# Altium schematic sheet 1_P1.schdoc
size 307 x 218 mm; Symbol: Sheet-Symbol_A4; Device: Sheet-Symbol_A4; Company: SEIKAN Inc.; Drawed: Feryquence; Reviewed: Feryquence; Version: V2.06; Page Size: A4; @Project Name: Akari NEW; @Page Count: 1; @Update Date: 2025-08-06; @Create Date: 2025-07-07; @Schematic Name: Schematic1_1; @Page No: 1; @Page Name: P1; @Board Name: Plus; @Create Time: 18:45:47; @Update Time: 02:56:45; Width: 1170; Height: 825; Region Start: 1; X Region Count: 6; Y Region Count: 4; Blade Width: 10; Title Block Position: 3
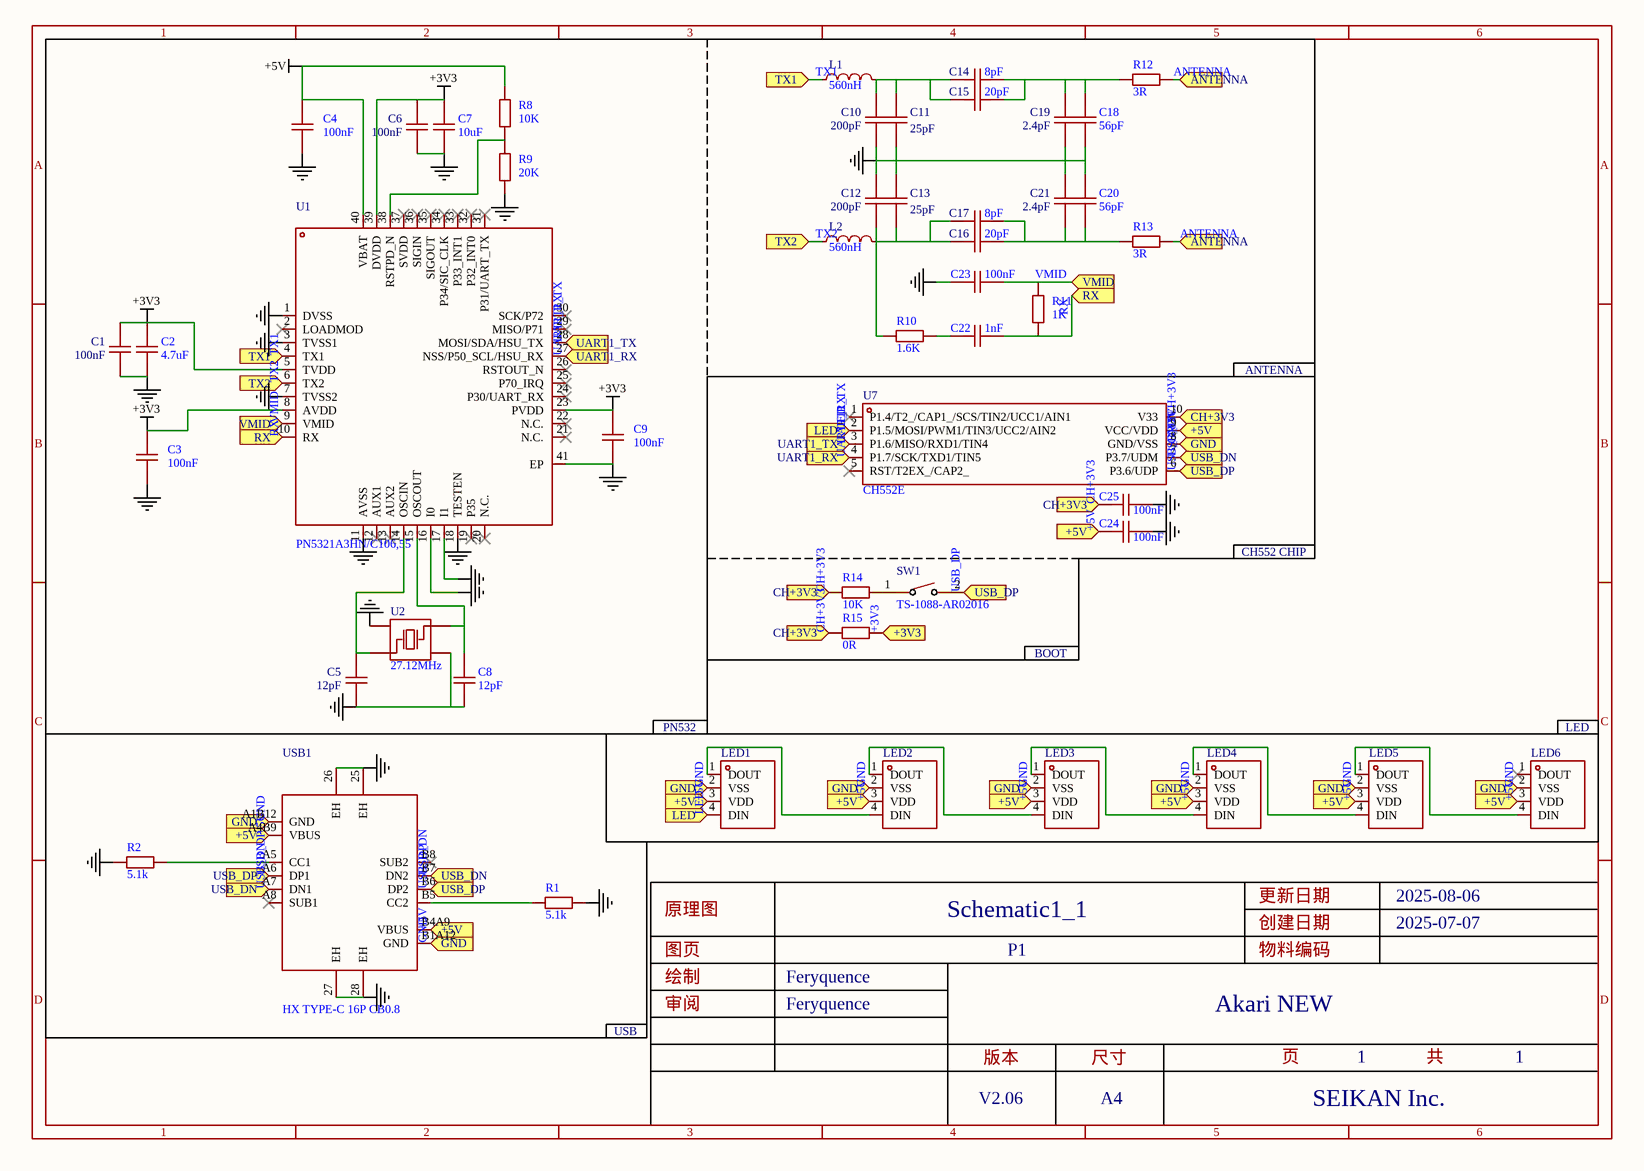
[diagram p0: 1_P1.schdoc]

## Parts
C1  100nF  [C0603]
C2  4.7uF  [C0603]
C3  100nF  [C0603]
C4  100nF  [C0603]
C5  12pF  [C0603]
C6  100nF  [C0603]
C7  10uF  [C0603]
C8  12pF  [C0603]
C9  100nF  [C0603]
C10  200pF  [C0603]
C11  25pF  [C0603]
C12  200pF  [C0603]
C13  25pF  [C0603]
C14  8pF  [C0603]
C15  20pF  [C0603]
C16  20pF  [C0603]
C17  8pF  [C0603]
C18  56pF  [C0603]
C19  2.4pF  [C0603]
C20  56pF  [C0603]
C21  2.4pF  [C0603]
C22  1nF  [C0603]
C23  100nF  [C0603]
C24  100nF  [C0603]
C25  100nF  [C0603]
L1  560nH  [L0805]
L2  560nH  [L0805]
LED1  3512侧面幻彩SK6812B-3512  [LED-SMD_SK6812B-3512]  (value not drawn)
LED2  3512侧面幻彩SK6812B-3512  [LED-SMD_SK6812B-3512]  (value not drawn)
LED3  3512侧面幻彩SK6812B-3512  [LED-SMD_SK6812B-3512]  (value not drawn)
LED4  3512侧面幻彩SK6812B-3512  [LED-SMD_SK6812B-3512]  (value not drawn)
LED5  3512侧面幻彩SK6812B-3512  [LED-SMD_SK6812B-3512]  (value not drawn)
LED6  3512侧面幻彩SK6812B-3512  [LED-SMD_SK6812B-3512]  (value not drawn)
R1  5.1k  [R0603]
R2  5.1k  [R0603]
R8  10K  [R0603]
R9  20K  [R0603]
R10  1.6K  [R0603]
R11  1K  [R0603]
R12  3R  [R0603]
R13  3R  [R0603]
R14  10K  [R0603]
R15  0R  [R0603]
SW1  TS-1088-AR02016  [SW-SMD_L3.9-W3.0-P4.45]
U1  PN5321A3HN/C106,55  [QFN-40_L6.0-W6.0-P0.50-BL-EP]
U2  27.12MHz  [CRYSTAL-SMD_4P-L2.0-W1.6-BL-2]
U7  CH552E  [MSOP-10_L3.0-W3.0-P0.50-LS5.0-BL]
USB1  HX TYPE-C 16P CB0.8  [USB-C-SMD_HX-TYPE-C-16P-CB0.8]

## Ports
+3V3 (in), +5V (in), ANTENNA (in), CH+3V3 (in), GND (in), LED (in), RX (in), TX1 (in), TX2 (in), UART1_RX (in), UART1_TX (in), USB_DN (in), USB_DP (in), VMID (in)

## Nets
+3V3: C1.2 C2.2 C3.2 C6.2 C7.2 C9.2 R15.2 U1.5(TVDD) U1.8(AVDD) U1.23(PVDD) U1.39(DVDD) ; port +3V3
+5V: C4.2 C24.1 LED1.3(VDD) LED2.3(VDD) LED3.3(VDD) LED4.3(VDD) LED5.3(VDD) LED6.3(VDD) R8.1 U1.40(VBAT) U7.9(VCC/VDD) USB1.A4B9(VBUS) USB1.B4A9(VBUS) ; port +5V
GND: C1.1 C2.1 C3.1 C4.1 C5.1 C6.1 C7.1 C8.1 C9.1 C10.1 C11.1 C12.1 C13.2 C18.1 C19.1 C20.1 C21.2 C23.2 C24.2 C25.2 LED1.2(VSS) LED2.2(VSS) LED3.2(VSS) LED4.2(VSS) LED5.2(VSS) LED6.2(VSS) R1.2 R2.1 R9.2 U1.1(DVSS) U1.3(TVSS1) U1.7(TVSS2) U1.11(AVSS) U1.16(I0) U1.17(I1) U1.18(TESTEN) U1.41(EP) U2.2(GND) U2.4(GND) U7.8(GND/VSS) USB1.25(EH) USB1.26(EH) USB1.27(EH) USB1.28(EH) USB1.A1B12(GND) USB1.B1A12(GND) ; port GND
ANTENNA: R12.2 R13.2 ; port ANTENNA
CH+3V3: C25.1 R14.1 R15.1 U7.10(V33) ; port CH+3V3
LED: LED1.4(DIN) U7.2(P1.5/MOSI/PWM1/TIN3/UCC2/AIN2) ; port LED
RX: C22.1 R11.1 U1.10(RX) ; port RX
TX1: L1.1 U1.4(TX1) ; port TX1
TX2: L2.1 U1.6(TX2) ; port TX2
UART1_RX: U1.27(NSS/P50_SCL/HSU_RX) U7.4(P1.7/SCK/TXD1/TIN5) ; port UART1_RX
UART1_TX: U1.28(MOSI/SDA/HSU_TX) U7.3(P1.6/MISO/RXD1/TIN4) ; port UART1_TX
USB_DN: U7.7(P3.7/UDM) USB1.A7(DN1) USB1.B7(DN2) ; port USB_DN
USB_DP: SW1.2 U7.6(P3.6/UDP) USB1.A6(DP1) USB1.B6(DP2) ; port USB_DP
VMID: C23.1 R11.2 U1.9(VMID) ; port VMID
NetC5_2: C5.2 U1.14(OSCIN) U2.1(IN/OUT)
NetC8_2: C8.2 U1.15(OSCOUT) U2.3(OUT/IN)
NetC10_2: C10.2 C11.2 C14.2 C15.2 L1.2
NetC12_2: C12.2 C13.1 C16.2 C17.2 L2.2 R10.1
NetC14_1: C14.1 C15.1 C18.2 C19.2 R12.1
NetC16_1: C16.1 C17.1 C20.2 C21.1 R13.1
NetC22_2: C22.2 R10.2
NetLED1_1: LED1.1(DOUT) LED2.4(DIN)
NetLED2_1: LED2.1(DOUT) LED3.4(DIN)
NetLED3_1: LED3.1(DOUT) LED4.4(DIN)
NetLED4_1: LED4.1(DOUT) LED5.4(DIN)
NetLED5_1: LED5.1(DOUT) LED6.4(DIN)
NetR1_1: R1.1 USB1.B5(CC2)
NetR2_2: R2.2 USB1.A5(CC1)
NetR8_2: R8.2 R9.1 U1.38(RSTPD_N)
NetR14_2: R14.2 SW1.1

Not connected (* = marked no-connect by the designer): LED6 1(DOUT)*; U1 2(LOADMOD)* 12(AUX1)* 13(AUX2)* 19(P35)* 20(N.C.)* 21(N.C.)* 22(N.C.)* 24(P30/UART_RX)* 25(P70_IRQ)* 26(RSTOUT_N)* 29(MISO/P71)* 30(SCK/P72)* 31(P31/UART_TX)* 32(P32_INT0)* 33(P33_INT1)* 34(P34/SIC_CLK)* 35(SIGOUT)* 36(SIGIN)* 37(SVDD)*; U7 1(P1.4/T2_/CAP1_/SCS/TIN2/UCC1/AIN1)* 5(RST/T2EX_/CAP2_)*; USB1 A8(SUB1)* B8(SUB2)*

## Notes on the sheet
- ANTENNA
- CH552 CHIP
- BOOT
- (near LED1) PN532
- LED
- USB

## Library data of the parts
C1-C25 = CAP_0603: Symbol: CapAcitance; Convert to PCB: yes
L1 L2 = SDFL2012LR56KTF: Manufacturer: Sunlord(顺络); Add into BOM: yes; Tolerance: ±10%; Rated Current: 150mA; DC Resistance(DCR): 750mΩ
LED1-LED6 = 3512侧面幻彩SK6812B-3512: Add into BOM: yes
R1 R2 R8-R15 = Res_0603: Symbol: 电阻; Convert to PCB: yes
SW1 = TS-1088-AR02016: Manufacturer: XUNPU(讯普); Add into BOM: yes; Circuit: 单刀单掷; Actuator Style: 圆形按钮; Operating Force: 160gf; Switch Length: 4mm; Switch Width: 3mm; Switch Height: 2mm; Strike Gundam: 不带; Contact Current: 50mA; Voltage Rating (DC): 12V; Insulation Resistance: 100MΩ; Actuator/Cap Color: 黑色; Pin Style: SMD接片; Mechanical Life: 10万次
U1 = PN5321A3HN/C106,55: Manufacturer: NXP(恩智浦); Add into BOM: yes
U2 = ECS-271.2-10-37-CKM-TR: Manufacturer: ECS; Add into BOM: yes; Normal temperature Frequency Tolerance: ±10ppm; External load capacitor: 10pF; Equivalent Series Resistance (ESR): 60Ω
U7 = CH552E: Manufacturer: WCH(南京沁恒); Add into BOM: yes; CPU Core: 51系列; Program Storage Size: 16KB; RAM Size: 1.25KB; Operating Voltage Range: 3.3V~5V; CPU Maximum Speed: 24MHz; Program Memory Type: FLASH; ADC (Bit): 8bit; 16Bit Timer: 3; UART/USART: 2; SPI: 1; Universal Serial Bus: 有; Peripheral/Function: DMA；看门狗；CCP捕获/比较；触控按键
USB1 = HX TYPE-C 16P CB0.8: Manufacturer: hanxia(韩下); Add into BOM: yes; Gender: 母; Number of Ports: 1; Current Rating - Power (Max): 3A; Rated Voltage (Max): 20V; Connect-Disconnect Life: 5千次; Core Colour: 黑色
